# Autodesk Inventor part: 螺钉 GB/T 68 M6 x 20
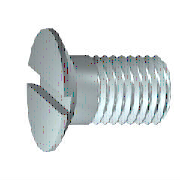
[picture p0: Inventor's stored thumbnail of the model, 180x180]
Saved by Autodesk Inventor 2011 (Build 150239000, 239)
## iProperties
Created: 2010-02
Part Number: 螺钉 GB/T 68 M6 x 20
Material: 低炭钢
Description: 开槽沉头螺钉
Document SubType Name: Modeling
Standard: GB/T 68-2000
Designer: Administrator
Standard Revision: 2000
Standards Organization: GB
Language: zh-CN
Size Designation: M6x20
Categories: <MemberInstance><Categories><Category DisplayName="紧固件" InternalName="e4da775c-781d-43d5-af7c-5136215cf5a6" Mnemonic="FSTN"><Category DisplayName="螺栓" InternalN
Density: 1 g/cm^3
IsCustomPart: 1
Author: Administrator
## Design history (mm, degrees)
body "Solid1"
sketch "Sketch1"
  geometry: L1 (3.625, 2.675)-(0.65, 5.65); L2 (0.65, 5.65)-(0, 5.65); L3 (0, 5.65)-(0, 0); L4 (0, 0)-(18, 0); L5 (18, 3)-(3.3, 3); L6 (3.3, 3)-(2.687, 2.675); L7 (2.687, 2.675)-(3.625, 2.675); L8 (3.3, 3)-(3.3, 3); L9 (18, 0)-(18, 3); L10 (-3.6, 0)-(21.6, 0) reference; L11 (0, 6.78)-(0, -1.13) reference
  constraints: 18 end point, 4 parallel, 2 collinear, 2 perpendicular, 1 horizontal, 1 point on line
  dimensions: "d0" = 18 distance of L3.end L4.end; "d1" = 45 deg angle of L1 L4 (= 0.5 x SEWI); "d2" = 0.61345 horizontal distance of L5.end L6.end (= GAL); "d3" = 14.7 distance from line of L9 L5.end (= GEL); "d4" = 3.3 distance from line of L8.end L3 (= KOH); "d5" = 5.351 diameter of L6.end L4 (= BDM); "d6" = 6 diameter of L5 L4 (= GD); "d7" = 11.3 diameter of L2 L4 (= KOD)
workplane "Work Plane1"
fillet "Fillet" dims "d41" = 1.5 (= RR)
revolve "Body" stored, may be unused: angle "d19" = 90 deg
sketch "Sketch2"
  geometry: L1 (5.65, -0.8)-(-5.65, -0.8); L2 (-5.65, -0.8)-(-5.65, 0.8); L3 (-5.65, 0.8)-(5.65, 0.8); L4 (5.65, 0.8)-(5.65, -0.8); L5 (0, 0.8)-(0, -0.8); L6 (-5.65, 0)-(5.65, 0); L7 (0, 5.65)-(0, 0) reference; 2 further points
  constraints: 12 end point, 5 midpoint, 2 parallel, 1 collinear, 1 horizontal, 1 perpendicular
  dimensions: "d15" = 1.6 distance of L3.end L1.start (= SBR); "d16" = 11.3 distance of L1.start L1.end (= KOD)
extrude "Slot" cut sketch "Sketch2" distance "d8" = 1.6 (= STI); taper "d9" = 0 deg
feature "Thread" dims "d10" = 14.7 (= GEL), "d11" = 0
chamfer "Chamfer1" distance "d12" = 0.61345 (= -0.5 x SPD + 0.5 x GD); stored, may be unused: second distance "d13" = 0.30673 (= 0.5 x GAL), angle "d35" = 45 deg
other parameters: "GAL" = 0.61345 (= 0.61345 x PTC) [user parameter; used in 2 equation terms], "GEL" = 14.7 [user parameter; used in 2 equation terms], "KOH" = 3.3 [user parameter; used in 1 equation term], "KOD" = 11.3 [user parameter; used in 2 equation terms], "SEWI" = 90 deg [user parameter; used in 1 equation term], "BDM" = 5.351 [user parameter; used in 1 equation term], "GD" = 6 (= NND) [user parameter; used in 2 equation terms], "SBR" = 1.6 [user parameter; used in 1 equation term], "STI" = 1.6 [user parameter; used in 1 equation term], "d17" = 0, "SPD" = 4.7731 (= NND - 1.2269 x PTC) [user parameter; used in 1 equation term], "d39" = 0, "d40" = 0, "RR" = 1.5 [user parameter; used in 1 equation term], "GUL" = 0.61345 (= 0.61345 x PTC) [user parameter], "PTC" = 1 [user parameter; used in 5 equation terms], "EPV" = 6.3 [user parameter], "THREADDIA" = 6 [user parameter; used in 1 equation term], "TOA" = 30 deg [user parameter], "FAWI" = 90 deg [user parameter], "NND" = 6 [user parameter; used in 2 equation terms], "GD1" = 4.7731 (= THREADDIA - 1.2269 x PTC) [user parameter]
